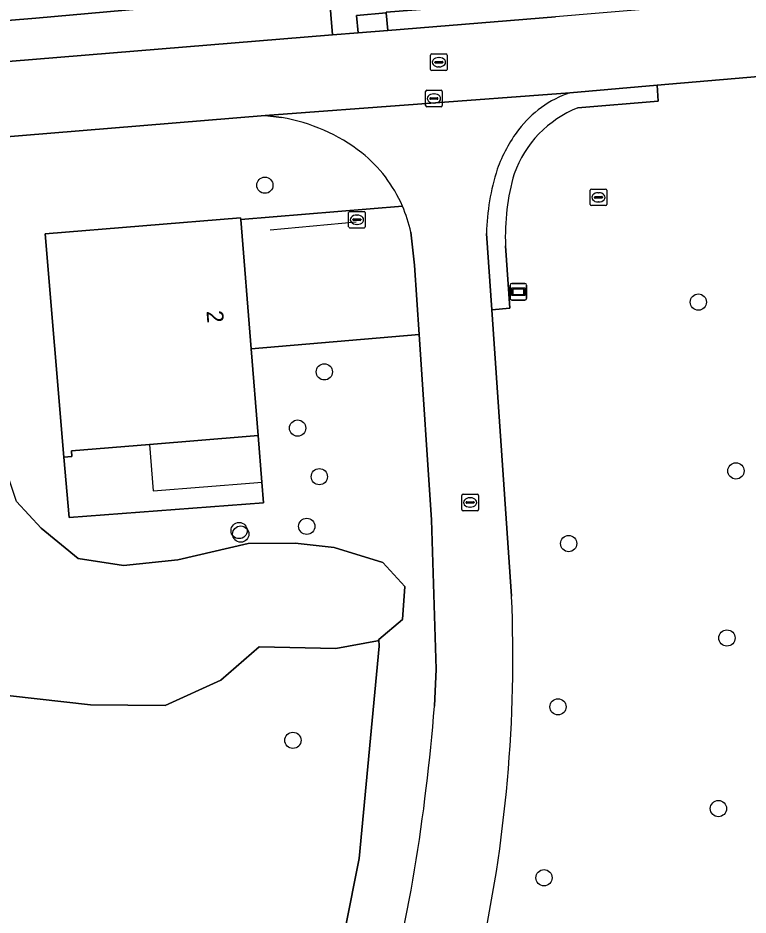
# Model space of a CAD drawing. Extents: x 156661 to 157576, y 383570 to 384425.
# Drawn here: x 157036.8 to 157080.7, y 383880.2 to 383934.2 of the extents above; entities that cross this region are included whole.
import ezdxf

# ---------------------------------------------------------------- set-up
doc = ezdxf.new("R2010")
doc.units = 0
for name, color, linetype in [('IMGEO_Berm_groen', 7, 'Continuous'), ('IMGEO_Boom', 7, 'Continuous'), ('IMGEO_Duiker', 7, 'Continuous'), ('IMGEO_Erf', 7, 'Continuous'), ('IMGEO_Groenvoorziening', 7, 'Continuous'), ('IMGEO_Kolk', 7, 'Continuous'), ('IMGEO_Meer_plas_ven_vijver', 7, 'Continuous'), ('IMGEO_Pand', 7, 'Continuous'), ('IMGEO_Pand_nummerreeks', 7, 'Continuous'), ('IMGEO_Pand_overbouw', 7, 'Continuous'), ('IMGEO_Parkeervlak_open', 7, 'Continuous'), ('IMGEO_Rijbaan_lokaal_open', 7, 'Continuous'), ('IMGEO_Rioolput', 7, 'Continuous'), ('IMGEO_Verklikker', 7, 'Continuous'), ('IMGEO_Voetpad_open', 7, 'Continuous')]:
    doc.layers.add(name, color=color, linetype=linetype)

msp = doc.modelspace()

# ---------------------------------------------------------------- linework, layer by layer
at = {"layer": 'IMGEO_Berm_groen'}
msp.add_lwpolyline([(157071.526, 383937.018), (157071.115, 383937.537), (157053.882, 383936.219), (157047.285, 383935.737), (157032.066, 383934.37), (156967.792, 383928.413), (156970.285, 383925.601), (156970.036, 383928.144), (156971.344, 383928.273), (156979.881, 383929.112), (156997.191, 383930.813), (157022.212, 383932.944), (157037.851, 383934.234), (157045.273, 383934.895), (157055.512, 383935.702), (157055.71, 383933.229), (157057.249, 383933.355), (157057.154, 383934.404), (157058.945, 383934.553), (157058.941, 383934.597), (157071.071, 383935.569)], dxfattribs=at)
at = {"layer": 'IMGEO_Boom'}
for centre in [(157051.638, 383924.178), (157077.734, 383917.141), (157055.216, 383912.939), (157053.608, 383909.552), (157079.996, 383906.975), (157054.915, 383906.628), (157054.16, 383903.639), (157050.088, 383903.385), (157050.185, 383903.171), (157069.925, 383902.602), (157079.454, 383896.915), (157069.283, 383892.77), (157053.327, 383890.755), (157078.941, 383886.643), (157068.442, 383882.478)]:
    msp.add_circle(centre, 0.489, dxfattribs=at)
at = {"layer": 'IMGEO_Duiker'}
msp.add_lwpolyline([(157051.962, 383921.488), (157057.129, 383921.981)], dxfattribs=at)
at = {"layer": 'IMGEO_Erf'}
for points in [[(157059.919, 383922.918), (157050.185, 383922.12), (157050.811, 383914.329), (157060.933, 383915.183), (157060.655, 383919.36)], [(157060.655, 383919.36), (157060.422, 383921.356)]]:
    msp.add_lwpolyline(points, dxfattribs=at)
msp.add_lwpolyline([(157051.231, 383909.101), (157050.754, 383909.062), (157044.688, 383908.566), (157039.992, 383908.182), (157040.02, 383907.838), (157039.527, 383907.797), (157039.856, 383904.163), (157051.555, 383905.062), (157051.456, 383906.299)], close=True, dxfattribs=at)
msp.add_arc((157052.052, 383919.523), 8.569, 12.3551, 23.3444, dxfattribs=at)
at = {"layer": 'IMGEO_Groenvoorziening'}
for points in [[(157101.55, 383932.451), (157075.258, 383930.194), (157075.311, 383929.234), (157070.476, 383928.831)], [(157052.643, 383928.253), (157051.661, 383928.368), (157025.823, 383926.256)], [(157061.843, 383892.809), (157061.944, 383895.031), (157061.676, 383904.039), (157060.933, 383915.183), (157050.811, 383914.329), (157051.231, 383909.101), (157051.456, 383906.299), (157051.555, 383905.062), (157039.856, 383904.163), (157039.527, 383907.797), (157038.419, 383921.247), (157050.177, 383922.218), (157050.185, 383922.12), (157059.919, 383922.918)], [(157066.126, 383920.528), (157066.39, 383916.783), (157065.301, 383916.677), (157066.491, 383899.424)], [(157036.688, 383905.124), (157038.179, 383903.527), (157040.392, 383901.697), (157043.135, 383901.271), (157046.402, 383901.626), (157050.624, 383902.606), (157053.467, 383902.626), (157055.804, 383902.363), (157058.737, 383901.453), (157060.073, 383900.008), (157059.933, 383898.037), (157058.506, 383896.82), (157058.511, 383896.433), (157057.323, 383883.635), (157055.608, 383875.059)]]:
    msp.add_lwpolyline(points, dxfattribs=at)
msp.add_lwpolyline([(157058.511, 383896.433), (157058.506, 383896.82), (157058.418, 383896.745), (157055.904, 383896.289), (157051.303, 383896.382), (157048.983, 383894.367), (157045.629, 383892.859), (157041.142, 383892.89), (157033.089, 383893.802), (157029.876, 383893.975), (157025.097, 383892.911), (157015.681, 383891.686), (157010.865, 383890.715), (157007.751, 383889.615), (157005.669, 383888.491), (157011.144, 383880.337), (157016.422, 383876.906), (157031.991, 383867.671), (157048.615, 383859.226), (157052.837, 383866.747), (157055.608, 383875.059), (157057.323, 383883.635)], close=True, dxfattribs=at)
for centre, radius, start, end in [((157072.921, 383922.641), 6.655, 111.5499, 160.4504), ((157050.792, 383917.472), 10.939, 52.3689, 80.2579), ((157052.159, 383919.553), 8.459, 23.4444, 51.0947), ((157079.53, 383921.114), 13.417, 163.7531, 182.5041), ((156982.068, 383895.793), 84.501, 347.43743, 2.46247), ((156950.957, 383901.264), 111.207, 345.40632, 355.63959)]:
    msp.add_arc(centre, radius, start, end, dxfattribs=at)
at = {"layer": 'IMGEO_Kolk'}
for p, q in [((157061.315, 383928.973), (157061.315, 383929.825)), ((157061.39, 383929.899), (157062.242, 383929.899)), ((157061.574, 383929.393), (157061.574, 383929.405)), ((157061.617, 383929.442), (157062.015, 383929.442)), ((157061.803, 383929.679), (157061.828, 383929.679)), ((157062.058, 383929.405), (157062.058, 383929.393)), ((157062.316, 383929.825), (157062.316, 383928.973)), ((157062.242, 383928.899), (157061.39, 383928.899)), ((157062.012, 383929.356), (157061.614, 383929.356)), ((157061.826, 383929.119), (157061.801, 383929.119))]:
    msp.add_line(p, q, dxfattribs=at)
for points in [[(157061.315, 383928.973), (157061.315, 383929.825)], [(157061.39, 383929.899), (157062.242, 383929.899)], [(157062.316, 383929.825), (157062.316, 383928.973)], [(157062.242, 383928.899), (157061.39, 383928.899)]]:
    msp.add_lwpolyline(points, dxfattribs=at)
for centre, radius, start, end in [((157061.392, 383929.823), 0.0765, 91.552, 178.448), ((157061.392, 383929.823), 0.0765, 91.552, 178.448), ((157061.614, 383929.402), 0.0403, 85.8775, 175.7526), ((157061.611, 383929.392), 0.0366, 178.938, 274.7102), ((157062.015, 383929.399), 0.043, 264.8664, 352.4533), ((157062.019, 383929.404), 0.0386, 1.7309, 96.639), ((157062.24, 383929.823), 0.0765, 1.552, 88.448), ((157062.24, 383929.823), 0.0765, 1.552, 88.448), ((157061.392, 383928.975), 0.0765, 181.552, 268.448), ((157061.392, 383928.975), 0.0765, 181.552, 268.448), ((157062.24, 383928.975), 0.0765, 271.552, 358.448), ((157062.24, 383928.975), 0.0765, 271.552, 358.448)]:
    msp.add_arc(centre, radius, start, end, dxfattribs=at)
for centre, major_axis, ratio, start_param, end_param in [((157061.802, 383929.399), (-0.387, 0.002), 0.722429, 4.712389, 7.853982), ((157061.827, 383929.399), (-0.39, 0.002), 0.717154, 1.570796, 4.712389)]:
    msp.add_ellipse(centre, major_axis=major_axis, ratio=ratio, start_param=start_param, end_param=end_param, dxfattribs=at)
at = {"layer": 'IMGEO_Meer_plas_ven_vijver'}
for points in [[(157058.506, 383896.82), (157059.933, 383898.037), (157060.073, 383900.008), (157058.737, 383901.453), (157055.804, 383902.363), (157053.467, 383902.626), (157050.624, 383902.606), (157046.402, 383901.626), (157043.135, 383901.271), (157040.392, 383901.697), (157038.179, 383903.527), (157036.688, 383905.124), (157035.009, 383910.135), (157035.099, 383912.828), (157035.651, 383914.934), (157034.883, 383918.999), (157033.92, 383920.439), (157031.544, 383920.294), (157030.153, 383917.093), (157030.381, 383909.178), (157030.882, 383902.825), (157029.834, 383900.645), (157025.386, 383899.558), (157018.935, 383897.895)], [(156965.319, 383894.998), (156975.842, 383894.559), (156983.208, 383893.538), (156986.656, 383893.993), (156988.991, 383893.36), (156994.479, 383890.731), (156998.463, 383889.523), (156999.413, 383889.244), (156999.755, 383888.928), (157002.231, 383886.636), (157005.669, 383888.491), (157007.751, 383889.615), (157010.865, 383890.715), (157015.681, 383891.686), (157025.097, 383892.911), (157029.876, 383893.975), (157033.089, 383893.802), (157041.142, 383892.89), (157045.629, 383892.859), (157048.983, 383894.367), (157051.303, 383896.382), (157055.904, 383896.289), (157058.418, 383896.745), (157058.506, 383896.82)]]:
    msp.add_lwpolyline(points, dxfattribs=at)
at = {"layer": 'IMGEO_Pand'}
msp.add_lwpolyline([(157050.185, 383922.12), (157050.177, 383922.218), (157038.419, 383921.247), (157039.527, 383907.797), (157040.02, 383907.838), (157039.992, 383908.182), (157044.688, 383908.566), (157050.754, 383909.062), (157051.231, 383909.101), (157050.811, 383914.329)], close=True, dxfattribs=at)
at = {"layer": 'IMGEO_Pand_overbouw'}
msp.add_lwpolyline([(157051.231, 383909.101), (157050.754, 383909.062), (157044.688, 383908.566), (157044.911, 383905.773), (157050.971, 383906.26), (157051.456, 383906.299)], close=True, dxfattribs=at)
at = {"layer": 'IMGEO_Parkeervlak_open'}
msp.add_lwpolyline([(157055.71, 383933.229), (157055.512, 383935.702), (157045.273, 383934.895), (157037.851, 383934.234), (157022.212, 383932.944), (156997.191, 383930.813), (156979.881, 383929.112), (156971.344, 383928.273), (156970.036, 383928.144), (156970.285, 383925.601), (156970.506, 383925.623), (157009.562, 383929.446)], close=True, dxfattribs=at)
at = {"layer": 'IMGEO_Rijbaan_lokaal_open'}
for points in [[(157025.823, 383926.256), (157051.661, 383928.368), (157069.999, 383929.742), (157075.258, 383930.194), (157101.55, 383932.451), (157099.825, 383936.843), (157080.659, 383935.273), (157071.766, 383934.544), (157069.139, 383934.324), (157059.045, 383933.502), (157057.249, 383933.355), (157055.71, 383933.229), (157009.562, 383929.446)], [(157071.071, 383935.569), (157058.941, 383934.597), (157058.945, 383934.553), (157059.045, 383933.502), (157069.139, 383934.324)], [(157075.258, 383930.194), (157069.999, 383929.742)], [(157070.476, 383928.831), (157075.311, 383929.234), (157075.258, 383930.194)], [(157069.999, 383929.742), (157051.661, 383928.368), (157052.643, 383928.253)], [(157060.422, 383921.356), (157060.655, 383919.36), (157060.933, 383915.183), (157061.676, 383904.039), (157061.944, 383895.031), (157061.843, 383892.809)], [(157064.983, 383921.279), (157065.301, 383916.677), (157066.39, 383916.783), (157066.126, 383920.528)], [(157066.491, 383899.424), (157065.301, 383916.677), (157064.983, 383921.279)]]:
    msp.add_lwpolyline(points, dxfattribs=at)
for centre, radius, start, end in [((157072.058, 383923.641), 6.439, 108.6496, 143.0244), ((157072.058, 383923.641), 6.439, 108.6496, 143.0244), ((157072.921, 383922.641), 6.655, 111.5499, 160.4504), ((157050.792, 383917.472), 10.939, 52.3689, 80.2579), ((157073.636, 383922.34), 8.483, 142.4135, 160.7612), ((157073.636, 383922.34), 8.483, 142.4135, 160.7612), ((157052.159, 383919.553), 8.459, 23.4444, 51.0947), ((157078.409, 383921.018), 13.429, 162.1486, 178.8882), ((157078.409, 383921.018), 13.429, 162.1486, 178.8882), ((157079.53, 383921.114), 13.417, 163.7531, 182.5041), ((157052.052, 383919.523), 8.569, 12.3551, 23.3444), ((156982.068, 383895.793), 84.501, 347.43743, 2.46247), ((156950.957, 383901.264), 111.207, 345.40632, 355.63959)]:
    msp.add_arc(centre, radius, start, end, dxfattribs=at)
at = {"layer": 'IMGEO_Rioolput'}
for p, q in [((157061.614, 383931.153), (157061.614, 383932.005)), ((157061.689, 383932.079), (157062.541, 383932.079)), ((157061.873, 383931.573), (157061.873, 383931.585)), ((157061.916, 383931.622), (157062.314, 383931.622)), ((157062.102, 383931.859), (157062.127, 383931.859)), ((157062.357, 383931.585), (157062.357, 383931.573)), ((157062.615, 383932.005), (157062.615, 383931.153)), ((157062.541, 383931.079), (157061.689, 383931.079)), ((157062.311, 383931.536), (157061.913, 383931.536)), ((157062.125, 383931.299), (157062.1, 383931.299)), ((157071.219, 383923.022), (157071.219, 383923.874)), ((157071.294, 383923.948), (157072.146, 383923.948)), ((157071.478, 383923.442), (157071.478, 383923.454)), ((157071.521, 383923.491), (157071.919, 383923.491)), ((157071.707, 383923.728), (157071.732, 383923.728)), ((157071.962, 383923.454), (157071.962, 383923.442)), ((157072.22, 383923.874), (157072.22, 383923.022)), ((157072.146, 383922.948), (157071.294, 383922.948)), ((157071.916, 383923.405), (157071.518, 383923.405)), ((157071.73, 383923.168), (157071.705, 383923.168)), ((157056.682, 383921.675), (157056.682, 383922.527)), ((157056.757, 383922.601), (157057.609, 383922.601)), ((157057.17, 383922.381), (157057.195, 383922.381)), ((157057.683, 383922.527), (157057.683, 383921.675)), ((157056.941, 383922.095), (157056.941, 383922.107)), ((157057.379, 383922.058), (157056.981, 383922.058)), ((157056.984, 383922.144), (157057.382, 383922.144)), ((157057.425, 383922.107), (157057.425, 383922.095)), ((157057.609, 383921.601), (157056.757, 383921.601)), ((157057.193, 383921.821), (157057.168, 383921.821)), ((157063.493, 383904.652), (157063.493, 383905.504)), ((157063.568, 383905.578), (157064.42, 383905.578)), ((157063.752, 383905.072), (157063.752, 383905.084)), ((157063.795, 383905.121), (157064.193, 383905.121)), ((157063.981, 383905.358), (157064.006, 383905.358)), ((157064.236, 383905.084), (157064.236, 383905.072)), ((157064.494, 383905.504), (157064.494, 383904.652)), ((157064.42, 383904.578), (157063.568, 383904.578)), ((157064.19, 383905.035), (157063.792, 383905.035)), ((157064.004, 383904.798), (157063.979, 383904.798))]:
    msp.add_line(p, q, dxfattribs=at)
for points in [[(157061.614, 383931.153), (157061.614, 383932.005)], [(157061.689, 383932.079), (157062.541, 383932.079)], [(157062.615, 383932.005), (157062.615, 383931.153)], [(157062.541, 383931.079), (157061.689, 383931.079)], [(157071.219, 383923.022), (157071.219, 383923.874)], [(157071.294, 383923.948), (157072.146, 383923.948)], [(157072.22, 383923.874), (157072.22, 383923.022)], [(157072.146, 383922.948), (157071.294, 383922.948)], [(157056.682, 383921.675), (157056.682, 383922.527)], [(157056.757, 383922.601), (157057.609, 383922.601)], [(157057.683, 383922.527), (157057.683, 383921.675)], [(157057.609, 383921.601), (157056.757, 383921.601)], [(157063.493, 383904.652), (157063.493, 383905.504)], [(157063.568, 383905.578), (157064.42, 383905.578)], [(157064.494, 383905.504), (157064.494, 383904.652)], [(157064.42, 383904.578), (157063.568, 383904.578)]]:
    msp.add_lwpolyline(points, dxfattribs=at)
for centre, radius, start, end in [((157061.691, 383932.003), 0.0765, 91.552, 178.448), ((157061.691, 383932.003), 0.0765, 91.552, 178.448), ((157061.913, 383931.582), 0.0403, 85.8775, 175.7526), ((157061.91, 383931.572), 0.0366, 178.938, 274.7102), ((157062.314, 383931.579), 0.043, 264.8664, 352.4533), ((157062.318, 383931.584), 0.0386, 1.7309, 96.639), ((157062.539, 383932.003), 0.0765, 1.552, 88.448), ((157062.539, 383932.003), 0.0765, 1.552, 88.448), ((157061.691, 383931.155), 0.0765, 181.552, 268.448), ((157061.691, 383931.155), 0.0765, 181.552, 268.448), ((157062.539, 383931.155), 0.0765, 271.552, 358.448), ((157062.539, 383931.155), 0.0765, 271.552, 358.448), ((157071.296, 383923.872), 0.0765, 91.552, 178.448), ((157071.296, 383923.872), 0.0765, 91.552, 178.448), ((157071.518, 383923.451), 0.0403, 85.8775, 175.7526), ((157071.923, 383923.453), 0.0386, 1.7309, 96.639), ((157072.144, 383923.872), 0.0765, 1.552, 88.448), ((157072.144, 383923.872), 0.0765, 1.552, 88.448), ((157071.296, 383923.024), 0.0765, 181.552, 268.448), ((157071.296, 383923.024), 0.0765, 181.552, 268.448), ((157071.515, 383923.441), 0.0366, 178.938, 274.7102), ((157071.919, 383923.448), 0.043, 264.8664, 352.4533), ((157072.144, 383923.024), 0.0765, 271.552, 358.448), ((157072.144, 383923.024), 0.0765, 271.552, 358.448), ((157056.759, 383922.525), 0.0765, 91.552, 178.448), ((157056.759, 383922.525), 0.0765, 91.552, 178.448), ((157057.607, 383922.525), 0.0765, 1.552, 88.448), ((157057.607, 383922.525), 0.0765, 1.552, 88.448), ((157056.981, 383922.104), 0.0403, 85.8775, 175.7526), ((157056.978, 383922.094), 0.0366, 178.938, 274.7102), ((157057.382, 383922.101), 0.043, 264.8664, 352.4533), ((157057.386, 383922.106), 0.0386, 1.7309, 96.639), ((157056.759, 383921.677), 0.0765, 181.552, 268.448), ((157056.759, 383921.677), 0.0765, 181.552, 268.448), ((157057.607, 383921.677), 0.0765, 271.552, 358.448), ((157057.607, 383921.677), 0.0765, 271.552, 358.448), ((157063.57, 383905.502), 0.0765, 91.552, 178.448), ((157063.57, 383905.502), 0.0765, 91.552, 178.448), ((157063.792, 383905.081), 0.0403, 85.8775, 175.7526), ((157064.197, 383905.083), 0.0386, 1.7309, 96.639), ((157064.418, 383905.502), 0.0765, 1.552, 88.448), ((157064.418, 383905.502), 0.0765, 1.552, 88.448), ((157063.57, 383904.654), 0.0765, 181.552, 268.448), ((157063.57, 383904.654), 0.0765, 181.552, 268.448), ((157063.789, 383905.071), 0.0366, 178.938, 274.7102), ((157064.193, 383905.078), 0.043, 264.8664, 352.4533), ((157064.418, 383904.654), 0.0765, 271.552, 358.448), ((157064.418, 383904.654), 0.0765, 271.552, 358.448)]:
    msp.add_arc(centre, radius, start, end, dxfattribs=at)
for centre, major_axis, ratio, start_param, end_param in [((157062.101, 383931.579), (-0.387, 0.002), 0.722429, 4.712389, 7.853982), ((157062.126, 383931.579), (-0.39, 0.002), 0.717154, 1.570796, 4.712389), ((157071.706, 383923.448), (-0.387, 0.002), 0.722429, 4.712389, 7.853982), ((157071.731, 383923.448), (-0.39, 0.002), 0.717154, 1.570796, 4.712389), ((157057.169, 383922.101), (-0.387, 0.002), 0.722429, 4.712389, 7.853982), ((157057.194, 383922.101), (-0.39, 0.002), 0.717154, 1.570796, 4.712389), ((157063.98, 383905.078), (-0.387, 0.002), 0.722429, 4.712389, 7.853982), ((157064.005, 383905.078), (-0.39, 0.002), 0.717154, 1.570796, 4.712389)]:
    msp.add_ellipse(centre, major_axis=major_axis, ratio=ratio, start_param=start_param, end_param=end_param, dxfattribs=at)
at = {"layer": 'IMGEO_Verklikker'}
for p, q in [((157066.398, 383917.36), (157066.398, 383918.16)), ((157066.398, 383918.16), (157066.398, 383917.36)), ((157066.498, 383918.26), (157067.288, 383918.26)), ((157067.288, 383918.26), (157066.498, 383918.26)), ((157067.388, 383918.16), (157067.388, 383917.36)), ((157067.388, 383917.36), (157067.388, 383918.16)), ((157067.288, 383917.26), (157066.498, 383917.26)), ((157066.498, 383917.26), (157067.288, 383917.26))]:
    msp.add_line(p, q, dxfattribs=at)
for points in [[(157066.499, 383917.992), (157067.287, 383917.992), (157067.287, 383917.528), (157066.499, 383917.528), (157066.499, 383917.992)], [(157066.564, 383917.927), (157066.564, 383917.593), (157067.222, 383917.593), (157067.222, 383917.927), (157066.564, 383917.927)]]:
    msp.add_lwpolyline(points, dxfattribs=at)
for centre, start, end in [((157066.498, 383918.16), 90, 180), ((157066.498, 383918.16), 90, 180), ((157067.288, 383918.16), 0, 90), ((157067.288, 383918.16), 360, 90), ((157066.498, 383917.36), 180, 270), ((157066.498, 383917.36), 180, 270), ((157067.288, 383917.36), 270, 0), ((157067.288, 383917.36), 270, 0)]:
    msp.add_arc(centre, 0.1, start, end, dxfattribs=at)
at = {"layer": 'IMGEO_Voetpad_open'}
msp.add_lwpolyline([(157058.945, 383934.553), (157057.154, 383934.404), (157057.249, 383933.355), (157059.045, 383933.502)], close=True, dxfattribs=at)

# ---------------------------------------------------------------- texts
at = {"layer": 'IMGEO_Pand_nummerreeks'}
msp.add_text('2', height=1, rotation=274.5949, dxfattribs=at).set_placement((157048.12, 383916.598))

doc.saveas('drawing.dxf')
